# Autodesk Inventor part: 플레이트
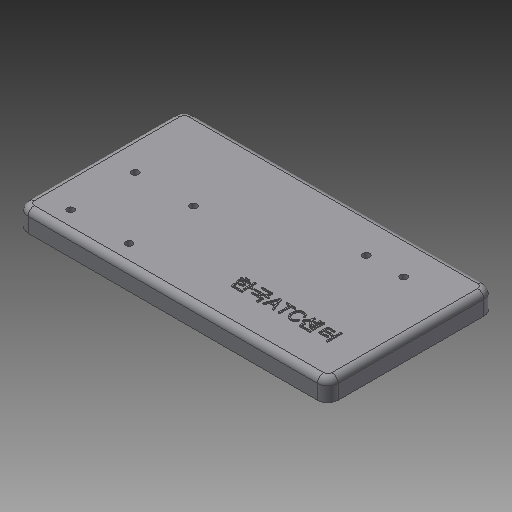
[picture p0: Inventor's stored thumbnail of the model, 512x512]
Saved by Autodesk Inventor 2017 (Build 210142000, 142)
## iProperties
Created: 2018-01
Part Number: 플레이트
Material: 알루미늄 6061
Document SubType Name: Modeling
Designer: mduedu
Density: 2.71 g/cm^3
Mass: 317.405 g
Surface Area: 285.843 cm^2
Volume: 117.124 cm^3
Appearance: 기본값
Author: mduedu
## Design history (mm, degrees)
sketch "스케치1"
  geometry: L1 (74.5, 40)-(-74.5, 40); L2 (-74.5, 40)-(-74.5, -40); L3 (-74.5, -40)-(74.5, -40); L4 (74.5, -40)-(74.5, 40); L5 (74.5, 40)-(-74.5, -40); L6 (-74.5, 40)-(74.5, -40); 1 further point
  constraints: 12 end point, 2 midpoint, 2 parallel, 1 horizontal, 1 perpendicular
  dimensions: "d0" = 149 distance of L3.end L2.end; "d1" = 80 distance of L2.end L1.end
extrude "돌출1" new body sketch "스케치1" distance "d2" = 10; taper "d3" = 0 deg
fillet "모깎기1" dims "d4" = 5
fillet "모깎기2" dims "d5" = 3
sketch "스케치2"
  geometry: L1 (-69.5, 40)-(69.5, 40) reference; L2 (-74.5, -35)-(-74.5, 35) reference; 5 further points
  constraints: 2 horizontal alignment, 2 vertical alignment
  dimensions: "d6" = 10 distance from line of point (-57.5, 30) L1; "d7" = 35 distance of point (-22.5, 30) point (-57.5, 30); "d8" = 31 distance of point (-57.5, -1) point (-57.5, 30); "d9" = 17 distance from line of point (-57.5, 30) L2
sketch "스케치3"
  geometry: L1 (-74.5, -35)-(-74.5, 35) reference; L2 (-69.5, 40)-(69.5, 40) reference; 4 further points
  constraints: 2 horizontal alignment, 2 vertical alignment
  dimensions: "d31" = 28 distance of point (-31, 30) point (-59, 30); "d33" = 15.5 distance from line of L1 point (-59, 30); "d34" = 10 distance from line of L2 point (-59, 30); "d35" = 31 distance of point (-59, -1) point (-59, 30)
hole "구멍1" sketch "스케치3" at (-31, 30), (-59, -1), (-31, -1), (-59, 30) diameter "d10" = 3.4; stored, may be unused: countersink angle "d14" = 90 deg, drill point angle "d16" = 0 deg; dims "d11" = 6, "d12" = 6.5, "d13" = 3.4, "d15" = 8
sketch "스케치4"
  geometry: L1 (74.5, 35)-(74.5, -35) reference; L2 (69.5, -40)-(-69.5, -40) reference; 3 further points
  constraints: 1 horizontal alignment
  dimensions: "d17" = 17 distance from line of point (57.5, -22) L1; "d18" = 18 distance of point (39.5, -22) point (57.5, -22); "d19" = 18 distance from line of point (57.5, -22) L2
sketch "스케치5"
  geometry: L1 (69.5, -40)-(-69.5, -40) reference; L2 (74.5, 35)-(74.5, -35) reference; 2 further points
  constraints: 1 horizontal alignment
  dimensions: "d36" = 18 distance from line of point (49, -22) L1; "d37" = 18 distance of point (31, -22) point (49, -22); "d38" = 25.5 distance from line of L2 point (49, -22)
hole "구멍2" sketch "스케치5" at (31, -22), (49, -22) diameter "d20" = 3.4; stored, may be unused: countersink angle "d24" = 90 deg, drill point angle "d26" = 0 deg; dims "d21" = 6, "d22" = 6.5, "d23" = 3.4, "d25" = 8
sketch "스케치6"
  geometry: L1 (74.5, -35)-(74.5, 35) reference; L2 (-69.5, -40)-(69.5, -40) reference; 2 further points
  constraints: 1 other
  dimensions: "d27" = 40 distance from line of point (34.5, -20) L1; "d28" = 20 distance from line of point (34.5, -20) L2
feature "엠보싱1" sketch "스케치6" dims "d0" = 149, "d29" = 0.5, "d30" = 0
node "솔리드1"
